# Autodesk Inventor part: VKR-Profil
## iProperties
Created: 2001-12
Part Number: VKR-Profil
Material: Steel, Mild
Description: VKR 75x75x3_375
Document SubType Name: Modeling
Designer: Tobben
Control State: 0
Master: False
Checked Out: False
Shininess: 64.0
Length Units: 11269
Angle Units: 11279
Time Units: 11290
Mass Units: 11283
Length Display Precision: 3
Angle Display Precision: 2
Density: 0.0
Volumn: 0.0
Area: 0.0
PropertySet Name: Model Information
Author: Tobben
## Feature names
1. Derived Body1 [Tagging]
